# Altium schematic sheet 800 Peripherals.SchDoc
size Letter; Organization: Toradex Solutions Inc.; Address1: 6415 Northwest Drive; Address2: Mississauga, ON, L4V 1X1; Address3: Canada
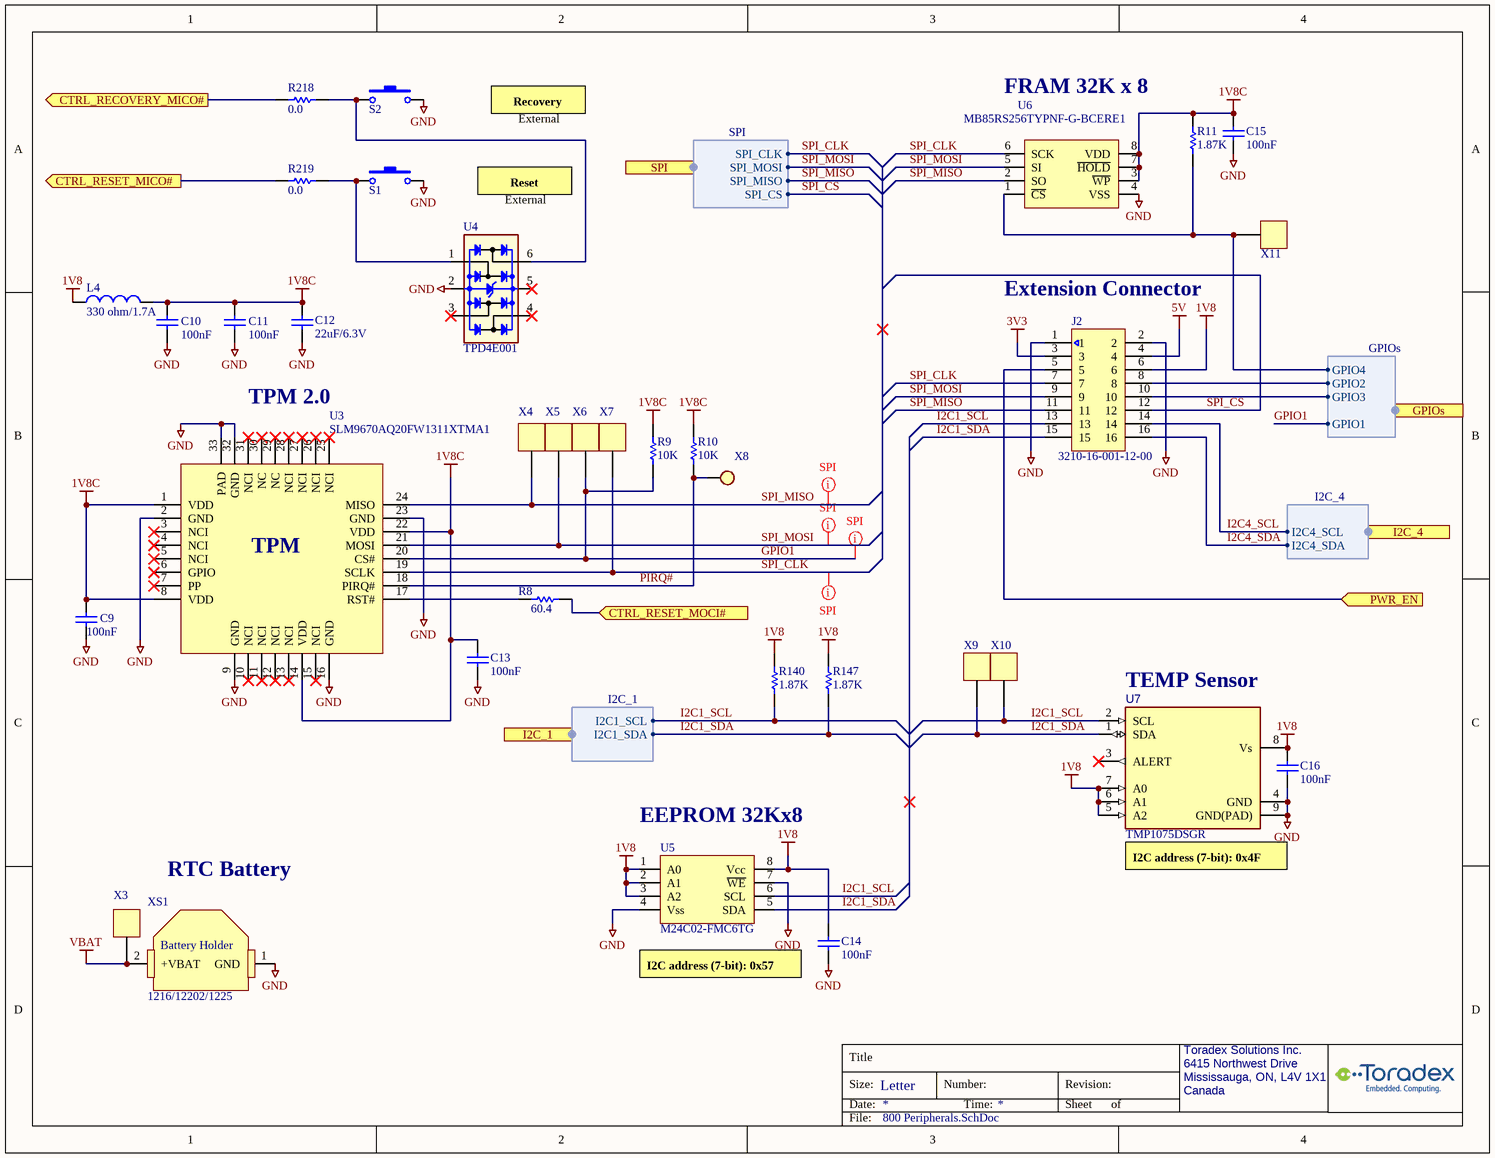
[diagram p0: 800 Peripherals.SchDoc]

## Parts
C9  100nF  [C0402_CAPC1005L]
C10  100nF  [C0402_CAPC1005L]
C11  100nF  [C0402_CAPC1005L]
C12  22uF/6.3V  [C0402_CAPC1005L]
C13  100nF  [C0402_CAPC1005L]
C14  100nF  [C0402_CAPC1005L]
C15  100nF  [C0402_CAPC1005L]
C16  100nF  [C0402_CAPC1005L]
J2  3210-16-001-12-00  [CNC_CONN16_3210-16-001-12-00]
L4  value 330 ohm/1.7A  [INDC1608x095]  (hidden comment: 0405-Fer-0603-330ohm/1.7A)
R8  value 60.4  [R/0603]  (hidden comment: 2199-Res-0603-60.4)
R9  value 10K  [R0402_RESC1005L]  (hidden comment: 1572-Res-0402-10K)
R10  value 10K  [R0402_RESC1005L]  (hidden comment: 1572-Res-0402-10K)
R11  value 1.87K  [R0402_RESC1005L]  (hidden comment: 1536-Res-0402-1.87K)
R140  value 1.87K  [R0402_RESC1005L]  (hidden comment: 1536-Res-0402-1.87K)
R147  value 1.87K  [R0402_RESC1005L]  (hidden comment: 1536-Res-0402-1.87K)
R218  value 0.0  [R/0603]  (hidden comment: 0195-Res-0603-0.0ohm)
R219  value 0.0  [R/0603]  (hidden comment: 0195-Res-0603-0.0ohm)
S1  PB  [BUTTON TC-1109DE-C-A]  (value not drawn)
S2  PB  [BUTTON TC-1109DE-C-A]  (value not drawn)
U3  SLM9670AQ20FW1311XTMA1  [QFN50P500X500X90-33N-V]
U4  TPD4E001  [SOT23-6]
U5  M24C02-FMC6TG  [M24C02FMC6TG]
U6  MB85RS256TYPNF-G-BCERE1  [SOIC-8]
U7  TMP1075DSGR  [WSON-8(2.1x2.1)_PAD]
X3  000-TestPoint  [TestPoint_1]  (value not drawn)
X4  000-TestPoint  [TestPoint_1]  (value not drawn)
X5  000-TestPoint  [TestPoint_1]  (value not drawn)
X6  000-TestPoint  [TestPoint_1]  (value not drawn)
X7  000-TestPoint  [TestPoint_1]  (value not drawn)
X8  000-TestPoint2  [TestPoint_3]  (value not drawn)
X9  000-TestPoint  [TestPoint_1]  (value not drawn)
X10  000-TestPoint  [TestPoint_1]  (value not drawn)
X11  000-TestPoint  [TestPoint_1]  (value not drawn)
XS1  1216/12202/1225  [T_KEYSTONE_3000]

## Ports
CTRL_RECOVERY_MICO# (out), CTRL_RESET_MICO# (out), CTRL_RESET_MOCI# (in), GPIOs (harness GPIOs), I2C_1 (harness I2C_1), I2C_4 (harness I2C_4), PWR_EN (in), SPI (harness SPI)

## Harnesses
I2C_1: I2C1_SDA, I2C1_SCL
I2C_4: I2C4_SDA, I2C4_SCL
SPI: SPI_CLK, SPI_MISO, SPI_MOSI, SPI_CS
GPIOs: GPIO4, GPIO2, GPIO3, GPIO1

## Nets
1V8: C14.2 C16.2 J2.6 L4.2 R140.2 R147.2 U5.1(A0) U5.2(A1) U5.3(A2) U5.8(Vcc) U7.5(A2) U7.6(A1) U7.7(A0) U7.8(Vs)
1V8C: C9.2 C10.2 C11.2 C12.2 C13.2 C15.2 L4.1 R9.2 R10.2 R11.2 U3.1(VDD) U3.8(VDD) U3.14(VDD) U3.22(VDD) U6.3(~{WP}) U6.7(~{HOLD}) U6.8(VDD)
3V3: J2.3
5V: J2.4
GND: C9.1 C10.1 C11.1 C12.1 C13.1 C14.1 C15.1 C16.1 J2.1 J2.2 S1.2 S2.2 U3.2(GND) U3.9(GND) U3.16(GND) U3.23(GND) U3.32(GND) U3.33(PAD) U4.2 U5.4(Vss) U5.7(~{WE}) U6.4(VSS) U7.4(GND) U7.9(GND(PAD)) XS1.1(GND)
VBAT: X3.1 XS1.2(+VBAT)
CTRL_RECOVERY_MICO#: R218.1 ; port CTRL_RECOVERY_MICO#
CTRL_RESET_MICO#: R219.1 ; port CTRL_RESET_MICO#
CTRL_RESET_MOCI#: R8.1 ; port CTRL_RESET_MOCI#
GPIO1: R9.1 U3.20(CS#) X6.1 ; port GPIOs.GPIO1
I2C1_SCL: J2.13 R140.1 U5.6(SCL) U7.2(SCL) X10.1 ; port I2C_1.I2C1_SCL
I2C1_SDA: J2.15 R147.1 U5.5(SDA) U7.1(SDA) X9.1 ; port I2C_1.I2C1_SDA
I2C4_SCL: J2.14 ; port I2C_4.I2C4_SCL
I2C4_SDA: J2.16 ; port I2C_4.I2C4_SDA
PIRQ#: R10.1 U3.18(PIRQ#) X8.1
PWR_EN: J2.5 ; port PWR_EN
SPI_CLK: J2.7 U3.19(SCLK) U6.6(SCK) X7.1 ; port SPI.SPI_CLK
SPI_CS: J2.12 ; port SPI.SPI_CS
SPI_MISO: J2.11 U3.24(MISO) U6.2(SO) X4.1 ; port SPI.SPI_MISO
SPI_MOSI: J2.9 U3.21(MOSI) U6.5(SI) X5.1 ; port SPI.SPI_MOSI
NetJ2_8: J2.8 ; port GPIOs.GPIO2
NetJ2_10: J2.10 ; port GPIOs.GPIO3
NetR8_2: R8.2 U3.17(RST#)
NetR11_1: R11.1 U6.1(~{CS}) X11.1 ; port GPIOs.GPIO4
NetR218_2: R218.2 S2.1 U4.6
NetR219_2: R219.2 S1.1 U4.1

Not connected (* = marked no-connect by the designer): U3 3(NCI)* 4(NCI)* 5(NCI)* 6(GPIO)* 7(PP)* 10(NCI)* 11(NCI)* 12(NCI)* 13(NCI)* 15(NCI)* 25(NCI)* 26(NCI)* 27(NCI)* 28(NCI)* 29(NC)* 30(NC)* 31(NCI)*; U4 3* 4* 5*; U7 3(ALERT)*

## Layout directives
net class SPI: GPIO1, SPI_CLK, SPI_MISO, SPI_MOSI

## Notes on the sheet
- FRAM 32K x 8
- Recovery
- External
- Reset
- (near J2) Extension Connector
- TPM 2.0
- (near U7) TEMP Sensor
- (near U5) EEPROM 32Kx8
- RTC Battery
- (near U7) I2C address (7-bit): 0x4F
- I2C address (7-bit): 0x57

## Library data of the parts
C9-C11 C13-C16 = 1566-Cap-0402-100nF/50V: (-55 to 125 DegC AEC) Cap Ceramic 0.1uF 50V X7R 10% 0402; MfrNo: GRT155R71H104KE01D; Mfr: Murata; Alt: CL05B104KB54PNC,GCM155R71H104ME02D,GCM155R71H104KE02D,GCM155R71H104KE02J; PN: 1566
C12 = 2404-Cap-0402-22uF/6.3V: (-55 to 85 DegC) CAP CER 22UF 6.3V 20% X5R 0402; MfrNo: GRM155R60J226ME11D; Mfr: Murata; PN: 2404
J2 = 2240-CONN-HDR 8x2 16POS 1.27MM: (-40 to 105 DegC) CONN HEADER VERT 8x2 16POS Shroud Latch Lock/Eject Hooks, Short 1.27MM SMT; Mfr: CNC Tech; PN: 2240
L4 = 0405-Fer-0603-330ohm/1.7A: (-55 to 125 DegC) FERRITE BEAD 330 OHM 0603 1.7A 80mohm, typ 48mohm; Mfr: TDK Corporation; MfrNo: MPZ1608S331ATA00; PN: 405; TR: 445-5221-2-ND; DR: 445-5221-6-ND; DR2: 810-MPZ1608S331ATA00
R8 = 2199-Res-0603-60.4: (-55 to 155 DegC) RES SMD 60.4 OHM 1% 1/10W 0603; MfrNo: CR0603-FX-60R4ELF; Mfr: Bourns; PN: 2199; Desc: (-55 to 155 DegC) RES SMD 60.4k OHM 1% 1/10W 0603
R9 R10 = 1572-Res-0402-10K: (-55 to 155 DegC AEC) RES 10K OHM 1% 1/16W 100ppm 0402; Mfr: Stackpole Electronics; MfrNo: RMCF0402FT10K0; Alt: AC0402FR-0710KL,AC0402FR-1310KL,CRGCQ0402F10K; PN: 1572
R11 R140 R147 = 1536-Res-0402-1.87K: (-55 to 155 DegC AEC) RES 1.87K OHM 1% 1/16W 100ppm 0402; MfrNo: RMCF0402FT1K87; Mfr: Stackpole Electronics; Alt: AC0402FR-071K87L,RK73H1ETTP1871F,ERJ-2RKF1871X; PN: 1536
R218 R219 = 0195-Res-0603-0.0ohm: RES 0.0 OHM 1/10W JUMP 0603; Mfr: Samsung; MfrNo: RC1608J000CS; PN: 195; Alt: 311-0.0GRCT-ND; Alt2: A106051CT-ND; TR: 1276-3510-2-ND
S1 S2 = 1226-Push Button: (-30 to 85 DegC) SWITCH TACTILE SPST-NO Push Button RA 4.5x2.8x4.5mm; Mfr: XKB Connectivity; MfrNo: TC-1109DE-C-A; PN: 1226
U3 = 1361-SLM9670: (-40 to 105 DegC) IC Trusted Platform TPM SECURITY 32-VFQFN; Mfr: Infineon; PN: 1361
U4 = 0740-TPD4E001: (-40 to 125 DegC AEC) TVS DIODE 5.5VWM 16VC SOT-23-6; MfrNo: TPD4E001QDBVRQ1; Mfr: Texas Instruments; PN: 740; Alt: TPD4E001DBVR
U5 = 1679-M24C02-FMC6TG: (-40 to 85 DegC) IC EEPROM 2KBIT (256B) 400KHZ 1.7-5.5V adr 0x50-57 2x3mm 8-UFDFN; Mfr: STMicroelectronics; PN: 1679
U6 = 1877-MB85RS256TY: (-40 to 125 DegC) IC FRAM Memory 1.8-3.6V 256Kbit 32x8KB SPI 33 MHz 8-SOIC; Mfr: Fujitsu; PN: 1877; Alt: MB85RS256TYPNF-G-AWERE2, MB85RS256TYPNF-GS-BCERE1
U7 = 1853-TMP1075DSGR: (-55 to 125 DegC) IC Temp Sensor I2C 1.7-5.5V WSON8; Mfr: Texas Instruments; PN: 1853
X3-X7 X9-X11 = 000-TestPoint: Note: this is PCB footprint only, no parts to buy or assemble
X8 = 000-TestPoint2: TestPoint SMD; Note: PCB footprint only, no parts to buy or assemble
XS1 = 1028-Conn-BatHolder-1220: (-40 to 105 DegC) Battery Holder Coin 12mm SMD 1216/1220/1225; MfrNo: 3000; Mfr: Keystone Electronics; PN: 1028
